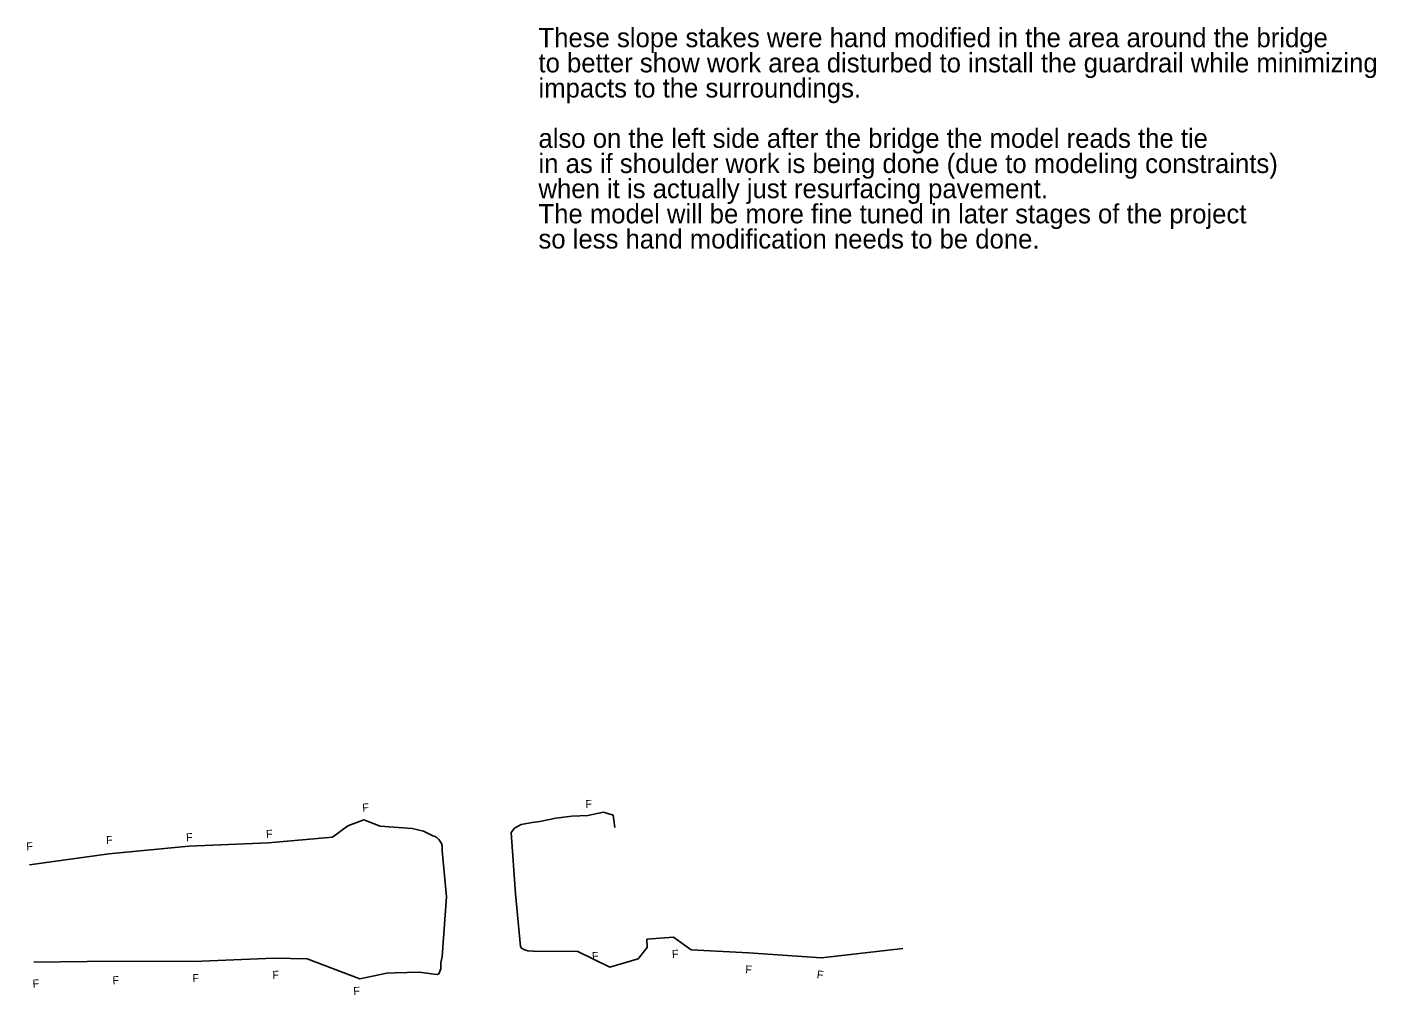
# Model space of a CAD drawing. Extents: x 1191331 to 1191753, y 893048 to 893350.
import ezdxf

# ---------------------------------------------------------------- set-up
doc = ezdxf.new("R2010")
doc.units = 0
for name, color, linetype in [('Prop DSN Text', 7, 'Continuous'), ('Prop SS Cut Line', 7, 'Continuous'), ('Prop SS Fill Line', 7, 'Continuous'), ('Prop SS Transition Line', 7, 'Continuous'), ('Prop Terminator CELL', 7, 'Continuous')]:
    doc.layers.add(name, color=color, linetype=linetype)

msp = doc.modelspace()

# ---------------------------------------------------------------- linework, layer by layer
at = {"layer": 'Prop SS Fill Line'}
for p, q in [((1191381.99, 893094.07), (1191406.97, 893095.1)), ((1191332.21, 893088.24), (1191357.08, 893091.66)), ((1191357.08, 893091.66), (1191381.99, 893094.07)), ((1191333.6, 893057.74), (1191358.62, 893058.04)), ((1191358.62, 893058.04), (1191383.64, 893058.03)), ((1191383.64, 893058.03), (1191408.62, 893059.05)), ((1191503.63, 893061.14), (1191513.54, 893056.23))]:
    msp.add_line(p, q, dxfattribs=at)
for points in [[(1191491.76, 893101.72), (1191496.72, 893102.75), (1191501.69, 893103.39), (1191506.69, 893103.6)], [(1191406.97, 893095.1), (1191426.88, 893096.86), (1191431.76, 893100.35)], [(1191431.76, 893100.35), (1191436.68, 893102.22), (1191441.77, 893100.29), (1191451.82, 893099.57)], [(1191451.82, 893099.57), (1191455.36, 893098.73), (1191458.23, 893097.29)], [(1191503.63, 893061.14), (1191489.66, 893061.23), (1191487.93, 893061.36), (1191486.69, 893061.69), (1191485.98, 893062.17), (1191485.71, 893062.71), (1191484.15, 893079.15), (1191482.71, 893098.29), (1191483.82, 893099.7), (1191485.91, 893100.85), (1191489.29, 893101.39), (1191491.76, 893101.72)], [(1191461.16, 893092.57), (1191462.51, 893078.16), (1191461.15, 893059.58), (1191460.78, 893057.56), (1191460.73, 893055.74), (1191460.17, 893054.16), (1191459.68, 893053.93), (1191457.89, 893054.11), (1191454.07, 893054.62), (1191446.37, 893054.4), (1191443.88, 893054.32)], [(1191525.17, 893064.95), (1191533.45, 893065.6)], [(1191533.45, 893065.6), (1191538.98, 893061.6), (1191556.86, 893060.72)], [(1191525.17, 893064.95), (1191525.28, 893062.4), (1191522.41, 893058.85), (1191513.54, 893056.23)], [(1191556.86, 893060.72), (1191579.74, 893059.12), (1191605.09, 893062.01)], [(1191408.62, 893059.05), (1191418.96, 893058.78), (1191435.42, 893052.55)], [(1191435.42, 893052.55), (1191443.88, 893054.32)]]:
    msp.add_lwpolyline(points, dxfattribs=at)
msp.add_arc((1191457.08, 893093.31), 4.15, 349.7847, 73.8359, dxfattribs=at)
at = {"layer": 'Prop SS Transition Line'}
msp.add_lwpolyline([(1191506.69, 893103.6), (1191511.65, 893104.64), (1191514.65, 893103.67), (1191515.13, 893099.87)], dxfattribs=at)
at = {"layer": 'Prop Terminator CELL'}
msp.add_line((1191579.74, 893059.12), (1191605.09, 893062.01), dxfattribs=at)

# ---------------------------------------------------------------- texts
at = {"layer": 'Prop DSN Text'}
for rotation, p in [(2.6195, (1191506.02, 893105.93)), (2.6195, (1191436.28, 893104.83)), (2.6195, (1191331.3, 893092.69)), (2.6195, (1191356.23, 893094.67)), (2.6195, (1191381.22, 893095.53)), (2.6195, (1191406.2, 893096.57)), (2.6195, (1191533.04, 893059.07)), (2.6195, (1191508.05, 893058.42)), (2.6195, (1191358.24, 893050.85)), (2.6195, (1191383.23, 893051.51)), (2.6195, (1191408.21, 893052.52)), (357.6322, (1191555.88, 893054.26)), (351.9026, (1191578.12, 893052.79)), (2.6195, (1191333.26, 893049.81)), (2.6195, (1191433.47, 893047.49))]:
    msp.add_text('F', height=2.5, rotation=rotation, dxfattribs=at).set_placement(p)
at = {"layer": 'Prop SS Cut Line'}
for s, p in [('These slope stakes were hand modified in the area around the bridge', (1191491.29, 893343.74)), ('to better show work area disturbed to install the guardrail while minimizing', (1191491.29, 893335.87)), ('impacts to the surroundings.', (1191491.29, 893328.01)), ('also on the left side after the bridge the model reads the tie ', (1191491.29, 893312.28)), ('in as if shoulder work is being done (due to modeling constraints) ', (1191491.29, 893304.41)), ('when it is actually just resurfacing pavement.', (1191491.29, 893296.55)), ('The model will be more fine tuned in later stages of the project', (1191491.29, 893288.68)), ('so less hand modification needs to be done.', (1191491.29, 893280.81))]:
    msp.add_text(s, height=6, dxfattribs=at).set_placement(p)

doc.saveas('drawing.dxf')
